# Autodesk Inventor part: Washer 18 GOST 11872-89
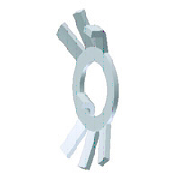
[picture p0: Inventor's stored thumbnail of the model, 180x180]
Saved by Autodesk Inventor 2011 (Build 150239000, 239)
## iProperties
IsCustomPart: 0
Created: 2010-02
Part Number: Washer 18 GOST 11872-89
Material: Steel, Mild
Description: Tongued lock washers
Document SubType Name: Modeling
Standard: GOST 11872-89
Designer: HTYCOON
Standards Organization: GOST
Language: en-US
Size Designation: 18
Categories: <MemberInstance><Categories><Category DisplayName="Fasteners" InternalName="e4da775c-781d-43d5-af7c-5136215cf5a6" Mnemonic="FSTN"><Category DisplayName="Washers
Mass: 0.958427 g
Surface Area: 3.91673 cm^2
Volume: 0.121937 cm^3
Density: 7.86 g/cm^3
Title: Шайба
Author: HTYCOON
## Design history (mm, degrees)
sketch "Sketch3"
  geometry: L1 (9.25, 1)-(12.222, 1); L2 (12.222, 1)-(13.475, 0.415); L3 (13.197, -0.558)-(13.053, -0.491); L4 (12, 0)-(9.25, 0); L5 (9.25, 0)-(9.25, 1); L6 (0, 1.883)-(0, -4.3) reference; L7 (14.903, 0)-(3.641, 0) reference; L8 (13.197, -0.558)-(13.197, -0.717); L9 (13.197, -4.288)-(14.197, -4.288); L10 (14.197, -4.288)-(14.197, -0.717); L11 (13.053, -0.491)-(12, 0); L12 (13.197, -0.717)-(13.197, -4.288); L13 (13.475, 0.415)-(14.197, 0.079); L14 (14.197, -0.717)-(14.197, 0.079); A1 r 3.862 centre (13.197, -0.558) between (14.197, -4.288) and (17, -1.228); A2 r 0.25 centre (12.947, -0.717) between (13.197, -0.717) and (13.053, -0.491); A3 r 1.25 centre (12.947, -0.717) between (14.197, -0.717) and (13.475, 0.415)
  constraints: 24 end point, 9 parallel, 8 tangent, 6 point on circle, 3 centre point, 3 perpendicular, 1 coincident, 1 collinear, 1 horizontal, 1 point on line
  dimensions: "d24" = 1 distance between parallel lines of L4 L1 (= S_); "d25" = 25 deg angle of L2 L1; "d26" = 24 diameter of L4.start L6 (= d3_); "d27" = 18.5 diameter of L5 L6 (= d1_); "d28" = 1 distance between parallel lines of L10 L8 (= S_); "d29" = 1 distance between parallel lines of L3 L2 (= S_); "d30" = 13.197 distance from line of L3.start L6 (= Bend_Distance + 0.5 x S_); "d31" = 115 deg angle of L8 L3 (derived); "d32" = 34 diameter of A1.end L6 (= d2_); "d41" = 0.25 radius of A2 (derived); "d42" = 1.25 radius of A3 (derived)
body "Solid1"
sketch "Sketch1"
  geometry: L1 (0, 25.2)-(0, -25.2) reference; L2 (-25.2, 0)-(25.2, 0) reference; L3 (-2.4, -11.758)-(2.4, -11.758); L4 (2.4, -11.758)-(2.4, -21.869); L5 (2.4, -21.869)-(-2.4, -21.869); L6 (-2.4, -21.869)-(-2.4, -11.758); L7 (0, 0)-(-1.72, 6.42); L8 (3.8, -11.382)-(7.957, -8.982); L9 (8.856, -20.139)-(3.8, -11.382); L10 (7.957, -8.982)-(13.013, -17.739); L11 (13.013, -17.739)-(8.856, -20.139); L12 (8.982, -7.957)-(11.382, -3.8); L13 (17.739, -13.013)-(8.982, -7.957); L14 (11.382, -3.8)-(20.139, -8.856); L15 (20.139, -8.856)-(17.739, -13.013); L16 (-13.766, 17.161)-(-17.161, 13.766); L17 (-15.464, 15.464)-(0, 0); L18 (-13.766, 17.161)-(-6.617, 10.011); L19 (-6.617, 10.011)-(-10.011, 6.617); L20 (-17.161, 13.766)-(-10.011, 6.617); L21 (-20.502, 7.978)-(-21.745, 3.342); L22 (-21.745, 3.342)-(-11.978, 0.725); L23 (-20.502, 7.978)-(-10.736, 5.361); L24 (-10.736, 5.361)-(-11.978, 0.725); L25 (-7.978, 20.502)-(-3.342, 21.745); L26 (-3.342, 21.745)-(-0.725, 11.978); L27 (-5.361, 10.736)-(-7.978, 20.502); L28 (-5.361, 10.736)-(0, 0); L29 (0, 0)-(-0.725, 11.978); L30 (-5.361, 10.736)-(-9.829, 19.682); L31 (-9.829, 19.682)-(-7.978, 20.502); L32 (3.106, 11.591)-(5.694, 21.25); L33 (-3.342, 21.745)-(5.694, 21.25); C1 r 9.25 at (0, 0); A1 r 22 centre (0, 0) between (-2.4, -21.869) and (-13.766, 17.161); A2 r 12 centre (0, 0) between (-2.4, -11.758) and (-10.011, 6.617); A3 r 12 centre (0, 0) between (3.106, 11.591) and (-0.725, 11.978); 1 further point
  constraints: 62 end point, 13 point on circle, 6 perpendicular, 4 centre point, 4 parallel, 2 coincident, 2 concentric, 2 equal length, 1 collinear, 1 horizontal, 1 midpoint, 1 point on line, 29 other
  dimensions: "d6" = 4.8 distance of L4.end L5.end (= b); "d7" = 15 deg angle of L1 L7; "d9" = 30 deg dimension on L7.start L3.start L8.start; "d16" = 24 diameter of A2 (= d3_); "d19" = 30 deg angle of L7 L17; "d23" = 18.5 diameter of C1 (= d1_); "d35" = 30 deg dimension on A1.centre L16.start L21.start; "d45" = 23.0739 deg angle of L29 L28 (derived); "d36" = 44 diameter of A1 (derived); "d37" = 15 deg angle of L32 L1
extrude "Extrusion1" new body sketch "Sketch1" stored distance "d21" = 20; taper "d22" = 0 deg
sketch "Sketch2"
  geometry: L1 (-4.484, 0)-(2.397, 0) reference; L2 (2.397, 0)-(-4.484, 0) reference; L3 (1, 9.25)-(0, 9.25); L4 (-2.134, 16.577)-(-1.228, 17); L5 (-1.228, 17)-(1, 12.222); L6 (-2.134, 16.577)-(0, 12); L7 (0, 9.25)-(0, 12); L8 (0, -10.55)-(0, 16.925) reference; L9 (-5, -5.75)-(-1, -5.75); L10 (1, -7.75)-(1, -10.625); L11 (1, -10.625)-(0, -10.625); L12 (0, -10.625)-(0, -7.75); L13 (-1, -6.75)-(-5, -6.75); L14 (-5, -6.75)-(-5, -5.75); L15 (1, 9.25)-(1, 12.222); A1 r 1 centre (-1, -7.75) between (0, -7.75) and (-1, -6.75); A2 r 2 centre (-1, -7.75) between (1, -7.75) and (-1, -5.75); A3 r 3.73 centre (-0.558, 13.197) between (-2.134, 16.577) and (-4.288, 13.197); 1 further point
  constraints: 24 end point, 6 perpendicular, 6 point on circle, 4 parallel, 4 tangent, 3 centre point, 2 collinear, 2 point on line, 1 horizontal alignment, 1 vertical
  dimensions: "d1" = 18.5 diameter of L3 L1 (= d1_); "d2" = 34 diameter of L4.end L1 (= d2_); "d3" = 1 distance between parallel lines of L5 L6 (= S_); "d4" = 24 diameter of L6.end L1 (= d3_); "d5" = 25 deg angle of L8 L5; "d10" = 1 radius of A1 (derived); "d11" = 2 radius of A2 (derived); "d12" = 6 distance between parallel lines of L10 L14 (= h_); "d13" = 21.25 diameter of L11 L1 (= 0.5 x d3_ + 0.5 x d1_); "d14" = 5.75 distance between parallel lines of L9 L1 (= L - 0.5 x d1); "d15" = 1 distance between parallel lines of L15 L7 (= S_); "d43" = 5.05058 distance of L4.start L6.end (derived); "d20" = 13.197 vertical distance of point (0, 0) A3.centre (= Bend_Distance + 0.5 x S_); "d44" = 3.72984 distance of A3.centre A3.end (derived)
revolve "Revolution1" stored, may be unused: angle "d102" = 90 deg
extrude "Extrusion2" join sketch "Sketch2" stored distance "d17" = 4.8 (= b); taper "d18" = 0 deg
workplane "Work Plane1"
revolve "Revolution2" stored, may be unused: angle "d33" = 23.0739 deg (derived)
extrude "Extrusion3" cut sketch "Sketch1" taper "d38" = 0 deg; stored distance "d140" = 10
other parameters: "d1_" = 18.5 [user parameter; used in 4 equation terms], "d2_" = 34 [user parameter; used in 2 equation terms], "d3_" = 24 [user parameter; used in 4 equation terms], "b" = 4.8 [user parameter; used in 2 equation terms], "L" = 15 [user parameter; used in 1 equation term], "h_" = 6 [user parameter; used in 1 equation term], "S_" = 1 [user parameter; used in 7 equation terms], "Bend_Distance" = 12.697 [user parameter; used in 2 equation terms], "Bend_Angle" = 115 deg [user parameter], "r" = 1 [user parameter], "d156" = 0, "d158" = 0
